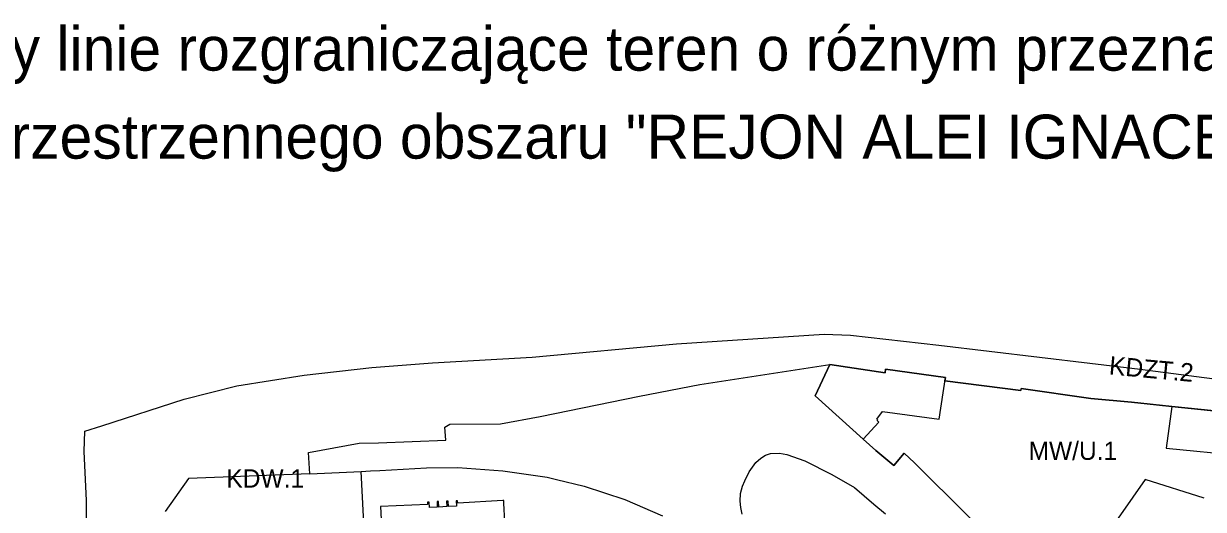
# Model space of a CAD drawing. Extents: x 7424052 to 7425705, y 5546602 to 5547569.
# Drawn here: x 7424650.3 to 7424972, y 5547436.7 to 5547569.3 of the extents above; entities that cross this region are included whole.
import ezdxf

# ---------------------------------------------------------------- set-up
doc = ezdxf.new("R2010")
doc.units = 0
for name, color, linetype in [('info', 7, 'Continuous'), ('linie rozgraniczające', 7, 'Continuous'), ('obowiazujace linie zabudowy', 7, 'Continuous'), ('przeznaczenia terenów', 7, 'Continuous')]:
    doc.layers.add(name, color=color, linetype=linetype)

msp = doc.modelspace()

# ---------------------------------------------------------------- linework, layer by layer
at = {"layer": 'linie rozgraniczające'}
for p, q in [((7424828.28, 5547481.86), (7424868.53, 5547484.52)), ((7424868.53, 5547484.52), (7424875.72, 5547484.24)), ((7424875.72, 5547484.24), (7424899.8, 5547481.56)), ((7424789.01, 5547478.29), (7424828.28, 5547481.86)), ((7424899.8, 5547481.56), (7424954.69, 5547474.96)), ((7424745.25, 5547475.43), (7424761.82, 5547476.67)), ((7424761.82, 5547476.67), (7424789.01, 5547478.29)), ((7424834.69, 5547470.82), (7424870.11, 5547476.25)), ((7424866.11, 5547467.66), (7424870.11, 5547476.25)), ((7424870.11, 5547476.25), (7424885.19, 5547474)), ((7424708.46, 5547470.45), (7424726.86, 5547473.36)), ((7424726.86, 5547473.36), (7424745.25, 5547475.43)), ((7424885.19, 5547474), (7424885.29, 5547474.96)), ((7424885.29, 5547474.96), (7424901.61, 5547472.67)), ((7424954.69, 5547474.96), (7425005.28, 5547468.49)), ((7424694.1, 5547466.81), (7424708.46, 5547470.45)), ((7424818.21, 5547467.62), (7424834.69, 5547470.82)), ((7424901.61, 5547472.67), (7424901.48, 5547471.82)), ((7424901.48, 5547471.82), (7424922.22, 5547469.17)), ((7424922.22, 5547469.17), (7424922.3, 5547469.68)), ((7424922.3, 5547469.68), (7424941.27, 5547466.94)), ((7424671.65, 5547459.49), (7424694.1, 5547466.81)), ((7424791.19, 5547462.1), (7424818.21, 5547467.62)), ((7424879.21, 5547455.87), (7424866.11, 5547467.66)), ((7424941.27, 5547466.94), (7424952.32, 5547465.95)), ((7424952.32, 5547465.95), (7424959.17, 5547465.25)), ((7424959.17, 5547465.25), (7424963.39, 5547464.82)), ((7424963.39, 5547464.82), (7424985.51, 5547462.54)), ((7424765.16, 5547459.15), (7424766.5, 5547459.99)), ((7424766.5, 5547459.99), (7424780.33, 5547460.06)), ((7424780.33, 5547460.06), (7424791.19, 5547462.1)), ((7424666.86, 5547452.48), (7424666.98, 5547458.06)), ((7424666.98, 5547458.06), (7424671.65, 5547459.49)), ((7424666.98, 5547458.06), (7424666.98, 5547458.06)), ((7424765.41, 5547455.59), (7424765.16, 5547459.15)), ((7424728.04, 5547452.23), (7424741.85, 5547454.8)), ((7424741.85, 5547454.8), (7424747.04, 5547454.88)), ((7424747.04, 5547454.88), (7424765.41, 5547455.59)), ((7424882.69, 5547452.8), (7424879.21, 5547455.87)), ((7424667.44, 5547439.14), (7424666.86, 5547452.48)), ((7424728.35, 5547446.39), (7424728.04, 5547452.23)), ((7424849.92, 5547449.5), (7424851.32, 5547450.74)), ((7424851.32, 5547450.74), (7424852.56, 5547451.53)), ((7424852.56, 5547451.53), (7424853.9, 5547451.94)), ((7424853.9, 5547451.94), (7424856.39, 5547452.08)), ((7424856.39, 5547452.08), (7424858.38, 5547451.68)), ((7424858.38, 5547451.68), (7424863.27, 5547449.99)), ((7424887.55, 5547448.67), (7424882.69, 5547452.8)), ((7424890.38, 5547452.05), (7424887.55, 5547448.67)), ((7424893.17, 5547449.41), (7424890.38, 5547452.05)), ((7424728.35, 5547446.39), (7424742.39, 5547447.09)), ((7424742.39, 5547447.09), (7424744.91, 5547447.21)), ((7424746.58, 5547360.62), (7424742.39, 5547447.09)), ((7424744.91, 5547447.21), (7424747.44, 5547447.34)), ((7424747.44, 5547447.34), (7424760.17, 5547448.04)), ((7424760.17, 5547448.04), (7424768.67, 5547448.12)), ((7424768.67, 5547448.12), (7424781, 5547447.26)), ((7424781, 5547447.26), (7424793.05, 5547445.51)), ((7424848.09, 5547447.01), (7424849.92, 5547449.5)), ((7424863.27, 5547449.99), (7424870.66, 5547446.26)), ((7424907.75, 5547434.92), (7424893.17, 5547449.41)), ((7424695.29, 5547445.12), (7424688.94, 5547436.14)), ((7424728.35, 5547446.39), (7424695.29, 5547445.12)), ((7424793.05, 5547445.51), (7424795.63, 5547444.89)), ((7424795.63, 5547444.89), (7424803.19, 5547443.05)), ((7424846.32, 5547443.08), (7424846.91, 5547444.47)), ((7424846.91, 5547444.47), (7424848.09, 5547447.01)), ((7424870.66, 5547446.26), (7424876.85, 5547442.65)), ((7424956.07, 5547444.88), (7424932.06, 5547410.56)), ((7424972.19, 5547439.75), (7424956.07, 5547444.88)), ((7424803.19, 5547443.05), (7424814.23, 5547439.39)), ((7424845.7, 5547438.98), (7424845.75, 5547441.04)), ((7424845.75, 5547441.04), (7424846.32, 5547443.08)), ((7424876.85, 5547442.65), (7424882.08, 5547438.18)), ((7424667.64, 5547422.58), (7424667.44, 5547439.14)), ((7424814.23, 5547439.39), (7424824.51, 5547434.93)), ((7424845.86, 5547437.28), (7424845.7, 5547438.98)), ((7424882.08, 5547438.18), (7424885.29, 5547435.55)), ((7424846.2, 5547435.45), (7424845.86, 5547437.28))]:
    msp.add_line(p, q, dxfattribs=at)
at = {"layer": 'obowiazujace linie zabudowy'}
for points in [[(7424963.39, 5547464.82), (7424952.32, 5547465.95), (7424941.27, 5547466.94), (7424922.3, 5547469.68), (7424922.22, 5547469.17), (7424901.48, 5547471.82), (7424901.61, 5547472.67), (7424885.29, 5547474.96), (7424885.19, 5547474), (7424870.11, 5547476.25), (7424866.11, 5547467.66), (7424879.21, 5547455.87), (7424882.69, 5547452.8), (7424887.55, 5547448.67), (7424890.38, 5547452.05), (7424893.17, 5547449.41), (7424907.75, 5547434.92), (7424917.69, 5547425.49), (7424921.99, 5547421.88), (7424932.06, 5547410.56)], [(7424879.21, 5547455.87), (7424883.5, 5547460.48), (7424883.02, 5547460.93), (7424883.18, 5547461.1), (7424882.9, 5547461.36), (7424884.51, 5547463.4), (7424899.91, 5547461.3), (7424901.61, 5547472.67)], [(7424999.57, 5547446.43), (7425002.02, 5547460.16), (7424997.79, 5547460.77), (7424997.82, 5547460.98), (7424989.69, 5547462.14), (7424989.66, 5547461.94), (7424985.51, 5547462.54), (7424963.39, 5547464.82), (7424961.8, 5547453.38), (7424982.24, 5547451.4), (7424981.99, 5547449.94), (7424981.3, 5547447.56), (7424979.18, 5547440.31), (7424984.6, 5547438.67), (7424987.18, 5547447.5), (7424988.38, 5547448.26), (7424993.08, 5547447.53), (7424993.35, 5547446.81), (7424992.63, 5547446.87), (7424992.52, 5547446.31), (7424995.47, 5547445.82), (7424996.85, 5547446.85), (7424999.57, 5547446.43)], [(7424781.49, 5547433.3), (7424781.25, 5547438.42), (7424781.22, 5547439.15), (7424780.96, 5547439.14), (7424768.67, 5547438.42), (7424768.63, 5547439.09), (7424768.23, 5547439.09), (7424768.3, 5547437.6), (7424766.12, 5547437.5), (7424766.04, 5547438.97), (7424765.64, 5547438.95), (7424765.7, 5547437.47), (7424763.51, 5547437.36), (7424763.45, 5547438.84), (7424763.05, 5547438.83), (7424763.11, 5547437.35), (7424760.94, 5547437.24), (7424760.85, 5547438.72), (7424760.45, 5547438.7), (7424760.48, 5547438.03), (7424747.61, 5547437.48), (7424749.88, 5547393.13)]]:
    msp.add_lwpolyline(points, dxfattribs=at)

# ---------------------------------------------------------------- texts
at = {"layer": 'info'}
for s, p in [('Materiał pomocniczy zawierający linie rozgraniczające teren o różnym przeznaczeniu i różnych warunkach zagospodarowania terenu, ', (7424420.28, 5547556.42)), ('opracowane w skali 1:1000 pochodzące z Miejscowego Planu Zagospodarowania Przestrzennego obszaru "REJON ALEI IGNACEGO DASZYŃSKIEGO" zatwierdzonego uchwałą RMK Nr CXIV/3010/18 z dnia 24 października 2018 r.', (7424050.89, 5547532.42))]:
    msp.add_text(s, height=12, dxfattribs=at).set_placement(p)
at = {"layer": 'przeznaczenia terenów'}
msp.add_text('KDZT.2', height=5, rotation=354.8511, dxfattribs=at).set_placement((7424946.09, 5547473.55))
for s, p in [('MW/U.1', (7424924.3, 5547450.22)), ('KDW.1', (7424705.61, 5547442.66))]:
    msp.add_text(s, height=5, dxfattribs=at).set_placement(p)

doc.saveas('drawing.dxf')
